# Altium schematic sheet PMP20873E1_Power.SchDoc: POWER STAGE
size 431 x 279 mm; Date: Not shown in title block; ApprovedBy: Not shown in title block; CheckedBy: Not shown in title block; Author: Not shown in title block; CompanyName: Not shown in title block; DrawnBy: Eric Faraci; Engineer: Not shown in title block; Organization: Not shown in title block; Address1: Not shown in title block; Address2: Not shown in title block; Address3: Not shown in title block; Address4: Not shown in title block; DocumentNumber: 1; Revision: E1; SheetNumber: 2; SheetTotal: 8; PageSetup: Record=PageOptions¦CenterHorizontal=True¦CenterVertical=True¦PrintScale=0.96¦XCorrection=1.00¦YCorrection=1.00¦PrintKind=0¦BorderSize=5000000¦LeftOffset=0¦BottomOffset=0¦Orientation=2¦PaperLength=1000¦PaperWidth=1000¦Scale=100¦PaperSource=15¦PrintQuality=600¦MediaType=1¦DitherType=10¦PaperKind=11x17¦PrintScaleMode=1
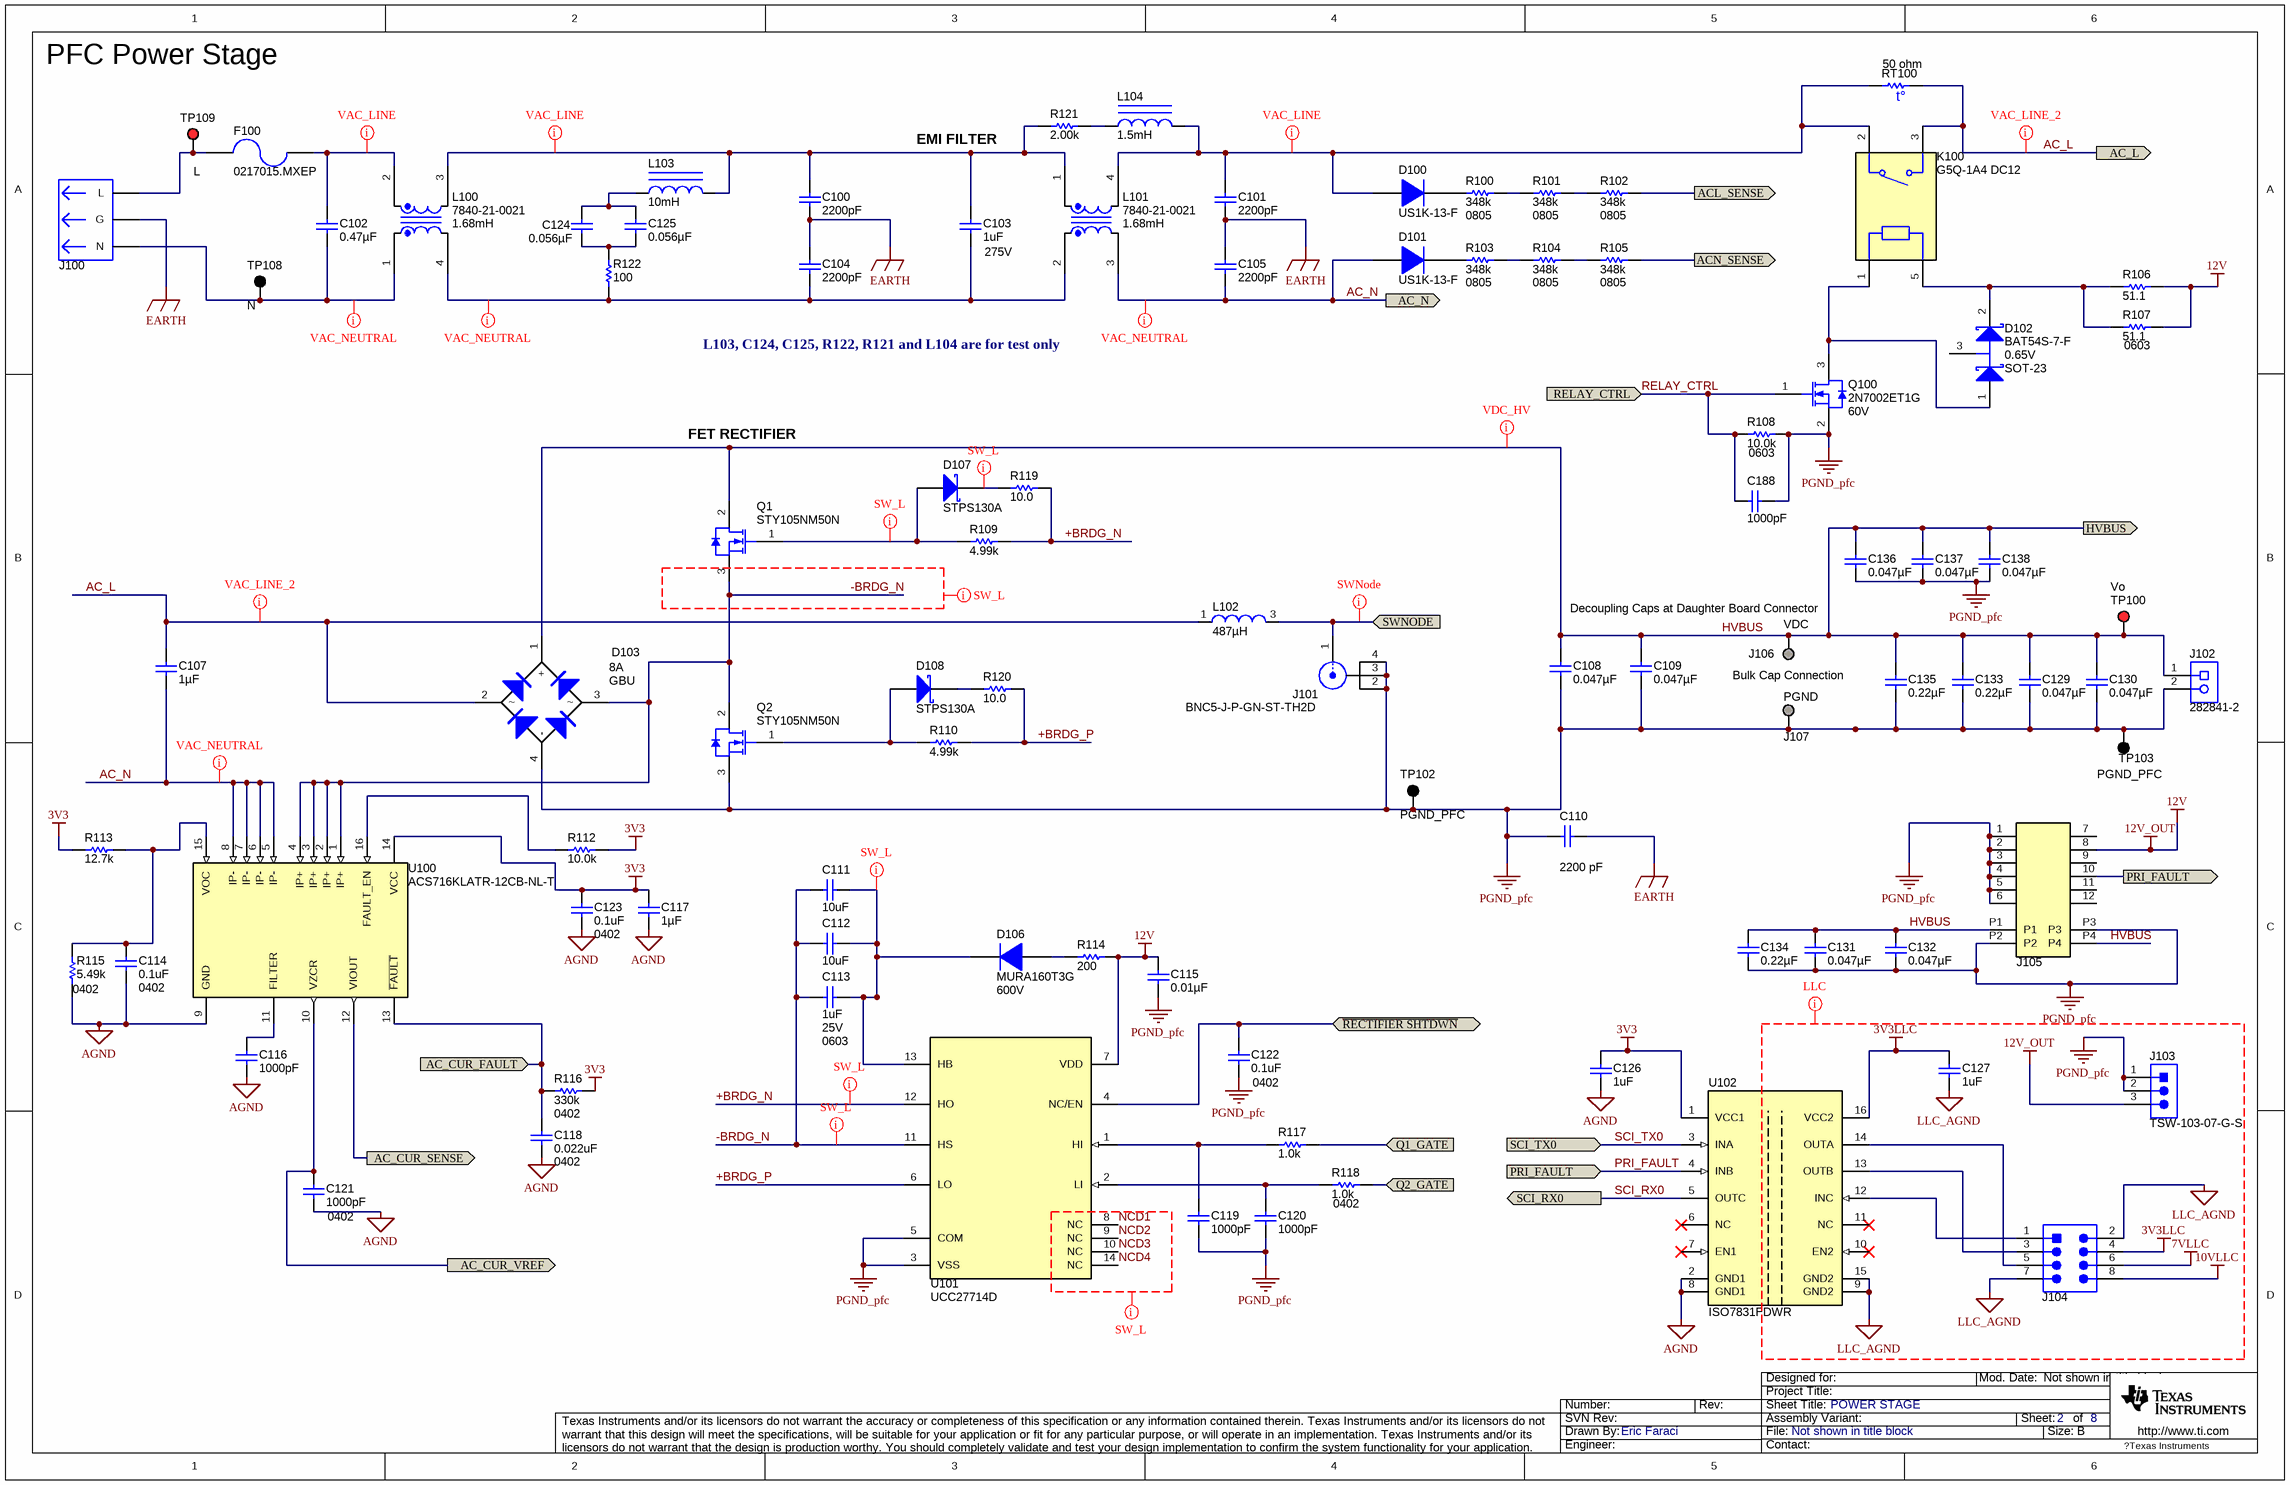
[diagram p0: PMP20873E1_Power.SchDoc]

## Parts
C100  ValueDisplayed: 2200pF  [CAPRD500W60D800H850]  (hidden comment: DE2E3KY222MA2BM01)
C101  ValueDisplayed: 2200pF  [CAPRD500W60D800H850]  (hidden comment: DE2E3KY222MA2BM01)
C102  ValueDisplayed: 0.47µF  [CAPRR2250W80L2550T850H1750]  (hidden comment: ECQ-U2A474ML)
C103  Value2: 275V  ValueDisplayed: 1uF  [CAPRR2250W80L2550T850H1750]  (hidden comment: R46KN-4100--P1 M)
C104  ValueDisplayed: 2200pF  [CAPRD500W60D800H850]  (hidden comment: DE2E3KY222MA2BM01)
C105  ValueDisplayed: 2200pF  [CAPRD500W60D800H850]  (hidden comment: DE2E3KY222MA2BM01)
C107  ValueDisplayed: 1µF  [MPK_1800x950]  (hidden comment: 450MPK105J)
C108  ValueDisplayed: 0.047µF  [1210]  (hidden comment: GRM32DR72J473KW01L)
C109  ValueDisplayed: 0.047µF  [1210]  (hidden comment: GRM32DR72J473KW01L)
C110  value 2200 pF  [CAPRD1000W60D900H1200]  (hidden comment: C921U222MYWDBA7317)
C111  ValueDisplayed: 10uF  [0805_HV]  (hidden comment: 0805YD106MAT2A)
C112  ValueDisplayed: 10uF  [0805_HV]  (hidden comment: 0805YD106MAT2A)
C113  ValueDisplayed: 1uF  Value2: 25V  [0603]  (hidden comment: C1608X7R1E105K080AB)
C114  ValueDisplayed: 0.1uF  [0402]  (hidden comment: GRM155R70J104KA01D)
C115  ValueDisplayed: 0.01µF  [0603]  (hidden comment: C0603X103K5RACTU)
C116  ValueDisplayed: 1000pF  [0603]  (hidden comment: C1608X7R1H102K)
C117  ValueDisplayed: 1µF  [0603]  (hidden comment: GRM185R60J105KE26D)
C118  ValueDisplayed: 0.022uF  [0402]  (hidden comment: GRM155R70J223KA01D)
C119  ValueDisplayed: 1000pF  [0402]  (hidden comment: C1005X7R1H102K)
C120  ValueDisplayed: 1000pF  [0402]  (hidden comment: GRM155R60J102KA01D)
C121  ValueDisplayed: 1000pF  [0402]  (hidden comment: GRM155R60J102KA01D)
C122  ValueDisplayed: 0.1uF  [0402]  (hidden comment: GRM155R70J104KA01D)
C123  ValueDisplayed: 0.1uF  [0402]  (hidden comment: GRM155R70J104KA01D)
C124  ValueDisplayed: 0.056µF  [2220_330_N]  (hidden comment: GA355XR7GB563KW06L)
C125  ValueDisplayed: 0.056µF  [2220_330_N]  (hidden comment: GA355XR7GB563KW06L)
C126  ValueDisplayed: 1uF  [0603]  (hidden comment: C1608X7R1E105K080AB)
C127  ValueDisplayed: 1uF  [0603]  (hidden comment: C1608X7R1E105K080AB)
C129  ValueDisplayed: 0.047µF  [1210]  (hidden comment: GRM32DR72J473KW01L)
C130  ValueDisplayed: 0.047µF  [1210]  (hidden comment: GRM32DR72J473KW01L)
C131  ValueDisplayed: 0.047µF  [1210]  (hidden comment: GRM32DR72J473KW01L)
C132  ValueDisplayed: 0.047µF  [1210]  (hidden comment: GRM32DR72J473KW01L)
C133  ValueDisplayed: 0.22µF  [2220]  (hidden comment: GRM55DR72J224KW01L)
C134  ValueDisplayed: 0.22µF  [2220]  (hidden comment: GRM55DR72J224KW01L)
C135  ValueDisplayed: 0.22µF  [2220]  (hidden comment: GRM55DR72J224KW01L)
C136  ValueDisplayed: 0.047µF  [1210]  (hidden comment: GRM32DR72J473KW01L)
C137  ValueDisplayed: 0.047µF  [1210]  (hidden comment: GRM32DR72J473KW01L)
C138  ValueDisplayed: 0.047µF  [1210]  (hidden comment: GRM32DR72J473KW01L)
C188  ValueDisplayed: 1000pF  [0603]  (hidden comment: GRM188R71C102KA01D)
D100  US1K-13-F  [SMA]
D101  US1K-13-F  [SMA]
D102  BAT54S-7-F  value 0.65V  [SOT-23]
D103  Value1: 8A  [GBU]  (hidden comment: GBU8J-BP)
D106  MURA160T3G  value 600V  [SMA]
D107  STPS130A  [SMA]
D108  STPS130A  [SMA]
F100  0217015.MXEP  [Fuse_217_015_Verical]
J100  703W-00/54  [CONN_QUALTEK-703W-0054]  (value not drawn)
J101  BNC5-J-P-GN-ST-TH2D  [Samtec_BNC5-J-P-GN-ST-TH2D]
J102  282841-2  [TEC_282841-2]
J103  TSW-103-07-G-S  [TSW-103-07-G-S]
J104  TSW-104-07-G-D  [TSW-104-07-G-D]  (value not drawn)
J105  PESC-02-12-02-01-L-RA-LC  [Samtec_PESC-02-12-02-01-x-RA-LC]  (value not drawn)
J106  VDC  [Mill-Max_0312-0-15-15-34-27-10-0]
J107  PGND  [Mill-Max_0312-0-15-15-34-27-10-0]
K100  G5Q-1A4 DC12  [Relay_G5Q-1A4]
L100  7840-21-0021  ValueDisplayed: 1.68mH  [7840-21-0021]
L101  7840-21-0021  ValueDisplayed: 1.68mH  [7840-21-0021]
L102  ValueDisplayed: 487µH  [IND_7840-09-0014]  (hidden comment: G164005LF)
L103  ValueDisplayed: 10mH  [ASPI-0403S]  (hidden comment: ASPI-0403S-103M-T)
L104  ValueDisplayed: 1.5mH  [LQH43M]  (hidden comment: LQH43MN152K03L)
Q1  STY105NM50N  [TO-247]
Q2  STY105NM50N  [TO-247]
Q100  2N7002ET1G  value 60V  [SOT-23]
R100  value 348k  PackageReference: 0805  [0805_HV]  (hidden comment: RT0805BRD07348KL)
R101  value 348k  PackageReference: 0805  [0805_HV]  (hidden comment: RT0805BRD07348KL)
R102  value 348k  PackageReference: 0805  [0805_HV]  (hidden comment: RT0805BRD07348KL)
R103  value 348k  PackageReference: 0805  [0805_HV]  (hidden comment: RT0805BRD07348KL)
R104  value 348k  PackageReference: 0805  [0805_HV]  (hidden comment: RT0805BRD07348KL)
R105  value 348k  PackageReference: 0805  [0805_HV]  (hidden comment: RT0805BRD07348KL)
R106  value 51.1  [0603]  (hidden comment: CRCW060351R1FKEA)
R107  value 51.1  [0603]  (hidden comment: CRCW060351R1FKEA)
R108  value 10.0k  [0603]  (hidden comment: RC0603FR-0710KL)
R109  ValueDisplayed: 4.99k  [0805_HV]  (hidden comment: ERJ-6ENF4991V)
R110  ValueDisplayed: 4.99k  [0805_HV]  (hidden comment: ERJ-6ENF4991V)
R112  value 10.0k  [0402]  (hidden comment: CRCW040210K0FKED)
R113  value 12.7k  [0402]  (hidden comment: CRCW040212K7FKED)
R114  value 200  [0603]  (hidden comment: CRCW0603200RFKEA)
R115  value 5.49k  [0402]  (hidden comment: CRCW04025K49FKED)
R116  value 330k  [0402]  (hidden comment: CRCW0402330KJNED)
R117  value 1.0k  [0402]  (hidden comment: CRCW04021K00JNED)
R118  value 1.0k  [0402]  (hidden comment: CRCW04021K00JNED)
R119  ValueDisplayed: 10.0  [0805_HV]  (hidden comment: CRCW080510R0FKEA)
R120  ValueDisplayed: 10.0  [0805_HV]  (hidden comment: CRCW080510R0FKEA)
R121  ValueDisplayed: 2.00k  [1206]  (hidden comment: CRCW12062K00FKEA)
R122  ValueDisplayed: 100  [1206]  (hidden comment: CRCW1206100RFKEA)
RT100  value 50 ohm  [TDK_B751]  (hidden comment: B59751B0120A070)
TP100  Vo  [Keystone5000]
TP102  PGND_PFC  [Keystone5001]
TP103  PGND_PFC  [Keystone5001]
TP108  N  [Keystone5001]
TP109  L  [Keystone5000]
U100  ACS716KLATR-12CB-NL-T  [SOIC-16]
U101  UCC27714D  [D0014A_N]
U102  ISO7831FDWR  [DW0016B_N]

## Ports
AC_CUR_FAULT, AC_CUR_SENSE, AC_CUR_VREF, AC_L, AC_N, ACL_SENSE, ACN_SENSE, HVBUS, PRI_FAULT (in), PRI_FAULT (out), Q1_GATE (in), Q2_GATE (in), RELAY_CTRL, SCI_RX0, SCI_TX0 (in), SWNODE, ~{RECTIFIER SHTDWN} (bidir)

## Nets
3V3: C117.1 C123.1 C126.2 R112.2 R113.2 R116.1 U100.14(VCC) U102.1(VCC1)
3V3LLC: C127.2 J104.4 U102.16(VCC2)
7VLLC: J104.6
10VLLC: J104.8
12V: C115.1 J103.3 J105.8 R106.2 R107.2 R114.2 U101.7(VDD)  [also labelled 12V_OUT]
AGND: C114.2 C116.2 C117.2 C118.1 C121.2 C123.2 C126.1 R115.1 U100.9(GND) U102.2(GND1) U102.8(GND1)
EARTH: C100.2 C101.2 C104.1 C105.1 C110.1 J100.3(G)
LLC_AGND: C127.1 J104.2 J104.7 U102.9(GND2) U102.15(GND2)
PGND_pfc: C108.2 C109.2 C110.2 C115.2 C119.2 C120.2 C122.2 C129.2 C130.2 C131.2 C132.2 C133.1 C134.2 C135.1 C136.2 C137.2 C138.2 C188.1 D103.4(-) J101.2 J101.3 J101.4 J102.2 J103.1 J103.2 J105.1 J105.2 J105.3 J105.4 J105.5 J105.6 J105.P2 J105.P3 J107.1 Q2.3(S) Q100.2(S) R108.2 TP102.1 TP103.1 U101.3(VSS) U101.5(COM)
+BRDG_N: R109.2 R119.2 U101.12(HO)
+BRDG_P: R110.2 R120.2 U101.6(LO)
-BRDG_N: C111.2 C112.2 C113.1 D103.3 Q1.3(S) Q2.2(D) U100.1(IP+) U100.2(IP+) U100.3(IP+) U100.4(IP+) U101.11(HS)
~{RECTIFIER SHTDWN}: C122.1 U101.4(NC/EN) ; port ~{RECTIFIER SHTDWN}
AC_CUR_FAULT: C118.2 R116.2 U100.13(~{FAULT}) ; port AC_CUR_FAULT
AC_CUR_SENSE: U100.12(VIOUT) ; port AC_CUR_SENSE
AC_CUR_VREF: C121.1 U100.10(VZCR) ; port AC_CUR_VREF
AC_L: C107.1 D103.2 K100.3 L102.1 RT100.2 ; port AC_L
AC_N: C105.2 C107.2 D101.2(A) L101.3 U100.5(IP-) U100.6(IP-) U100.7(IP-) U100.8(IP-) ; port AC_N
ACL_SENSE: R102.1 ; port ACL_SENSE
ACN_SENSE: R105.1 ; port ACN_SENSE
HVBUS: C108.1 C109.1 C129.1 C130.1 C131.1 C132.1 C133.2 C134.1 C135.2 C136.1 C137.1 C138.1 D103.1(+) J102.1 J105.P1 J105.P4 J106.1 Q1.2(D) TP100.1 ; port HVBUS
NCD1: U101.8(NC)
NCD2: U101.9(NC)
NCD3: U101.10(NC)
NCD4: U101.14(NC)
PRI_FAULT: J105.10 U102.4(INB) ; port PRI_FAULT
Q1_GATE: R117.2 ; port Q1_GATE
Q2_GATE: R118.2 ; port Q2_GATE
RELAY_CTRL: C188.2 Q100.1(G) R108.1 ; port RELAY_CTRL
SCI_RX0: U102.5(OUTC) ; port SCI_RX0
SCI_TX0: U102.3(INA) ; port SCI_TX0
SWNODE: J101.1 L102.3 ; port SWNODE
NetC100_1: C100.1 C103.1 L100.3 L101.1 L103.2 R121.1
NetC101_1: C101.1 D100.2(A) K100.2 L101.4 L104.2 RT100.1
NetC102_1: C102.1 F100.2 L100.2
NetC102_2: C102.2 J100.2(N) L100.1 TP108.1
NetC103_2: C103.2 C104.2 L100.4 L101.2 R122.1
NetC111_1: C111.1 C112.1 C113.2 D106.1(K) U101.13(HB)
NetC114_1: C114.1 R113.1 R115.2 U100.15(VOC)
NetC116_1: C116.1 U100.11(FILTER)
NetC119_1: C119.1 R117.1 U101.1(HI)
NetC120_1: C120.1 R118.1 U101.2(LI)
NetC124_1: C124.1 C125.1 L103.1
NetC124_2: C124.2 C125.2 R122.2
NetD100_1: D100.1(K) R100.2
NetD101_1: D101.1(K) R103.2
NetD102_1: D102.1(A) K100.1 Q100.3(D)
NetD102_2: D102.2(K) K100.5 R106.1 R107.1
NetD106_2: D106.2(A) R114.1
NetD107_1: D107.1(K) R119.1
NetD107_2: D107.2(A) Q1.1(G) R109.1
NetD108_1: D108.1(K) R120.1
NetD108_2: D108.2(A) Q2.1(G) R110.1
NetF100_1: F100.1 J100.1(L) TP109.1
NetJ104_1: J104.1 U102.12(INC)
NetJ104_3: J104.3 U102.13(OUTB)
NetJ104_5: J104.5 U102.14(OUTA)
NetL104_1: L104.1 R121.2
NetR100_1: R100.1 R101.2
NetR101_1: R101.1 R102.2
NetR103_1: R103.1 R104.2
NetR104_1: R104.1 R105.2
NetR112_1: R112.1 U100.16(FAULT_EN)

Not connected (* = marked no-connect by the designer): D102 3(C); J105 7 9 11 12; U102 6(NC)* 7(EN1)* 10(EN2)* 11(NC)*

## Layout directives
net class VAC_NEUTRAL: AC_N, NetC102_2, NetC103_2
net class VAC_LINE: NetC100_1, NetC101_1, NetC102_1
net class VAC_LINE_2: AC_L
net class SW_L: +BRDG_N, -BRDG_N, NCD1, NCD2, NCD3, NCD4, NetC111_1, NetD107_1, NetD107_2
net class LLC: 3V3LLC, 7VLLC, 10VLLC, 12V_OUT, LLC_AGND, PGND_pfc
net class VDC_HV: HVBUS
net class SWNode: SWNODE

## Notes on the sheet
- PFC Power Stage
- EMI FILTER
- L103, C124, C125, R122, R121 and L104 are for test only
- FET RECTIFIER
- Decoupling Caps at Daughter Board Connector
- Bulk Cap Connection

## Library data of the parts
C100 C101 C104 C105 = DE2E3KY222MA2BM01: CAP, CERM, 2200pF, 250V, +/-20%, KY, Radial D8x5mm; Manufacturer: MuRata; Polarized: N; CompType: Capacitor; U/M: EA; Cap_F: 0.0000000022; Tolerance_%: 20; Value1: Unknown; VDC_V: 250; TaMin_C: -25; TaMax_C: 85
C102 = ECQ-U2A474ML: CAP, Film, 0.47 µF, 275 V, +/- 20%, TH; Manufacturer: Panasonic; Polarized: N; CompType: Capacitor; Value: 0.47uF; U/M: EA; Cap_F: 0.00000047; Tolerance_%: 20; Value1: Unknown; VDC_V: 275; Value2: 275V; TaMin_C: -40; TaMax_C: 100; Cap_Case: Radial 25x8.5x18.5; AEC Category: Q200
C103 = ECQ-U2A474ML: CAP, Film, 1uF, 275V, +/-20%, TH; Manufacturer: Panasonic; Alternate PartNumber: R46KN410000P1M; Alternate Manufacturer: Kemet; Polarized: N; CompType: Capacitor; U/M: EA; Cap_F: 0.00000047; Tolerance_%: 20; Value1: Unknown; VDC_V: 275; TaMin_C: -40; TaMax_C: 100; Cap_Case: Radial 26x12x19.5
C107 = 450MPK105J: CAP, Film, 1 µF, 450 V, +/- 5%, TH; Manufacturer: Rubycon; Polarized: N; CompType: Capacitor; Value: 1uF; U/M: EA; Cap_F: 0.000001; Tolerance_%: 5; Value1: Unknown; VDC_V: 450; Value2: 450V; TaMin_C: -40; TaMax_C: 105; Cap_Case: 18x9.5mm; AEC Category: Q200
C108 C109 C129-C132 C136-C138 = GRM32DR72J473KW01L: CAP, CERM, 0.047 µF, 630 V, +/- 10%, X7R, 1210; Manufacturer: MuRata; Polarized: N; CompType: Capacitor; Value: 0.047uF; U/M: EA; Cap_F: 0.000000047; Tolerance_%: 10; Value1: Unknown; VDC_V: 630; Value2: 630V; TaMin_C: -55; TaMax_C: 125; AEC Category: Q200
C110 = DE1E3KX222MA4BL01: CAP, CERM, 2200pF, 250V, +/-20%, E, Cap, 7x12x9 mm TH; Manufacturer: Kemet; Tolerance_%: 20 %; Capacitance - nF: 2.2 nF; Capacitance - uF: 0.0022 uF; Case Diameter: 9 mm; TempCo: Y5U; Product Status: New Product
C111 C112 = 0805YD106MAT2A: CAP, CERM, 10uF, 16V, +/-20%, X5R, 0805; Manufacturer: AVX; Polarized: N; CompType: Capacitor; U/M: EA; Cap_F: 0.00001; Tolerance_%: 20; Value1: Unknown; VDC_V: 16; TaMin_C: -55; TaMax_C: 85; Cap_Case: 0805
C113 C126 C127 = C1608X7R1E105K080AB: CAP, CERM, 1uF, 25V, +/-10%, X7R, 0603; Manufacturer: TDK; Polarized: N; CompType: Capacitor; U/M: EA; Cap_F: 0.000001; Tolerance_%: 10; Value1: Unknown; VDC_V: 25; TaMin_C: -55; TaMax_C: 125
C114 C122 C123 = GRM155R70J104KA01D: CAP, CERM, 0.1uF, 6.3V, +/-10%, X7R, 0402; Manufacturer: MuRata; Polarized: N; CompType: Capacitor; U/M: EA; Cap_F: 0.0000001; Tolerance_%: 10; Value1: Unknown; VDC_V: 6.3; TaMin_C: -55; TaMax_C: 125
C115 = C0603X103K5RACTU: CAP, CERM, 0.01uF, 50V, +/-10%, X7R, 0603; Manufacturer: Kemet; Polarized: N; CompType: Capacitor; U/M: EA; Cap_F: 0.00000001; Tolerance_%: 10; Value1: Unknown; VDC_V: 50; TaMin_C: -55; TaMax_C: 125
C116 = C1608X7R1H102K: CAP, CERM, 1000pF, 50V, +/-10%, X7R, 0603; Manufacturer: TDK; Polarized: N; CompType: Capacitor; U/M: EA; Cap_F: 0.000000001; Tolerance_%: 10; ESR_Ohm: 0.24; Value1: 0.24 ohm; VDC_V: 50; TaMin_C: -55; TaMax_C: 125
C117 = GRM185R60J105KE26D: CAP, CERM, 1uF, 6.3V, +/-10%, X5R, 0603; Manufacturer: MuRata; Polarized: N; CompType: Capacitor; U/M: EA; Cap_F: 0.000001; Tolerance_%: 10; Value1: Unknown; VDC_V: 6.3; TaMin_C: -55; TaMax_C: 85
C118 = GRM155R70J223KA01D: CAP, CERM, 0.022uF, 6.3V, +/-10%, X7R, 0402; Manufacturer: MuRata; Polarized: N; CompType: Capacitor; U/M: EA; Cap_F: 0.000000022; Tolerance_%: 10; Value1: Unknown; VDC_V: 6.3; TaMin_C: -55; TaMax_C: 125
C119 = C1005X7R1H102K: CAP, CERM, 1000pF, 50V, +/-10%, X7R, 0402; Manufacturer: TDK; Polarized: N; CompType: Capacitor; U/M: EA; Cap_F: 0.000000001; Tolerance_%: 10; ESR_Ohm: 0.2381; Value1: 0.2381 ohm; VDC_V: 50; TaMin_C: -55; TaMax_C: 125
C120 C121 = GRM155R60J102KA01D: CAP, CERM, 1000pF, 6.3V, +/-10%, X5R, 0402; Manufacturer: MuRata; Polarized: N; CompType: Capacitor; U/M: EA; Cap_F: 0.000000001; Tolerance_%: 10; Value1: Unknown; VDC_V: 6.3; TaMin_C: -55; TaMax_C: 85
C124 C125 = GA355XR7GB563KW06L: CAP, CERM, 0.056 µF, 250 V, +/- 10%, X7R, 2220; Manufacturer: MuRata; Polarized: N; CompType: Capacitor; Value: 0.056uF; U/M: EA; Cap_F: 0.000000056; Tolerance_%: 10; Value1: Unknown; VDC_V: 250; Value2: 250V; TaMin_C: -55; TaMax_C: 125; Cap_Case: 2220; AEC Category: Q200
C133-C135 = GRM55DR72J224KW01L: CAP, CERM, 0.22 µF, 630 V, +/- 10%, X7R, 2220; Manufacturer: MuRata; Polarized: N; CompType: Capacitor; Value: 0.22uF; U/M: EA; Cap_F: 0.00000022; Tolerance_%: 10; Value1: Unknown; VDC_V: 630; Value2: 630V; TaMin_C: -55; TaMax_C: 125; AEC Category: Q200
C188 = GRM188R71C102KA01D: CAP, CERM, 1000pF, 16V, +/-10%, X7R, 0603; Manufacturer: MuRata; Polarized: N; CompType: Capacitor; U/M: EA; Cap_F: 0.000000001; Tolerance_%: 10; Value1: Unknown; VDC_V: 16; TaMin_C: -55; TaMax_C: 125
D100 D101 = US1K-13-F: Diode, Fast Rectifier, 800 V, 1 A, SMA; Manufacturer: Diodes Inc.; U/M: EA; Vf_V: 1.7; Value: 800V; Value1: 1A; Value2: 1.7V; Io_A: 1; Vr_V: 800; TJmax_C: 150; AEC Category: Q101
D102 = BAT54S-7-F: Diode, Schottky, 30V, 0.2A, SOT-23; Manufacturer: Diodes Inc.; U/M: EA; Vf_V: 0.65; Io_A: 0.2; Vr_V: 30; TJmax_C: 125
D103 = GBU8J-BP: Diode, Switching-Bridge, 420V, 8A, TH; Manufacturer: Micro Commercial Components; Value: 1V; U/M: EA; Vf_V: 1; Io_A: 8; Vr_V: 420; TJmax_C: 175
D106 = MURA160T3G: Diode, Ultrafast, 600V, 1A, SMA; Manufacturer: ON Semiconductor; U/M: EA; Vf_V: 1.05; Value2: 1.05V; Io_A: 1; Vr_V: 600; TJmax_C: 175
D107 D108 = STPS130A: Diode, Schottky, 30 V, 1 A, SMA; Manufacturer: STMicroelectronics; U/M: EA; Vf_V: 0.46; Value: 30V; Value1: 1A; Value2: 0.46V; Io_A: 1; Vr_V: 30; TJmax_C: 150; AEC Category: Q101
F100 = 0217015.MXEP: Fuse, 15 A, 250 V, TH; Manufacturer: Littelfuse; U/M: EA; VDC_V: 250; Irating_A: 15; Rtyp_Ohm: 0.04; MeltingTyp: 617.135; Vdrop: 0.13
J100 = 703W-00/54: AC Receptacle, 10A 250VAC; Manufacturer: Qualtek Electronics Corporation; SymbolCreator: a0799628; CompType: Connector; U/M: EA
J101 = BNC5-J-P-GN-ST-TH2D: 50 OHM BNC ELEVATED STRAIGHT JACK, TH; Manufacturer: Samtec; SymbolCreator: Altium; Gender: Male; ContactFinish: Gold
J102 = 282841-2: Terminal Block, 2x1, 5.08mm, TH; Manufacturer: TE Connectivity; SymbolCreator: a0412235; U/M: EA
J103 = TSW-103-07-G-S: Header, 100mil, 3x1, Gold, TH; Manufacturer: Samtec; SymbolCreator: a0799628; Pitch_mm: 2.54; Gender: Male; Shrouded: N; Row_Count: 1; Current_A: 6.3; Voltage_V: 550; Cert_CSA: Y
J104 = TSW-104-07-G-D: Header, 100mil, 4x2, Gold, TH; Manufacturer: Samtec; SymbolCreator: a0411947; Pitch_mm: 2.54; Gender: Male; Shrouded: N; Row_Count: 2; Current_A: 6.3; Voltage_V: 550; Cert_CSA: Y
J105 = PESC-02-12-02-01-L-RA-LC: Signal Power Combo Socket Strip, 4x3, 4 Power Group, R/A, Gold, TH; Manufacturer: Samtec; SymbolCreator: Altium; CompType: Power Connector; Pitch_mm: 2.54; Gender: Female; Row_Count: 3; Current_A: 40; Voltage_V: 650; Cert_UL: Y
J106 J107 = 0312-0-15-15-34-27-10-0: Pin Receptacle, .032-.046" .075" Dia, Gold, TH; Manufacturer: Mill-Max; U/M: EA
K100 = G5Q-1A4 DC12: Relay, SPST-NO (1 Form A), 10 A, 12 VDC, TH; Manufacturer: Omron Electronic Components; SymbolCreator: Altium; Coil Current: 16.7 mA; Coil Power: 200 mW; Coil Resistance: 720 ohms; Coil Type: Non Latching; Coil Voltage: 12 VDC; Contact Rating: 10 A; Turn Off Voltage (Min): 0.6 VDC; Turn On Voltage (Max): 9 VDC; Time Operate (s): 0.01; Time Release (s): 0.005
L100 L101 = 7840-21-0021: Coupled inductor, 1.68 mH,  A,  ohm, TH; Manufacturer: Nova Magnetics; SymbolCreator: a0799628; Value: 1.68mH; Ind_H: 1.7E-3
L102 = 7840-09-0014: Inductor, Toroid, Ferrite, 481 µH, 0.057 ohm, TH; Manufacturer: GCI technologies; SymbolCreator: a0411947; Value: 487uH; DCR_ohm: 0.057; Value2: A; AEC Category: Q200
L103 = ASPI-0403S-103M-T: Inductor, Wirewound, 10 mH, 0.02 A, 32.8 ohm, SMD; Manufacturer: Abracon Corporation; Value: 10mH; Ind_H: 10.0E-3; Imax_A: 0.02; DCR_ohm: 32.8; Value2: 0.02A; AEC Category: Q200; AEC Qualified: N
L104 = LQH43MN152K03L: Inductor, Wirewound, Ferrite, 1.5 mH, 0.04 A, 37 ohm, SMD; Manufacturer: MuRata; Value: 1.5mH; Ind_H: 1.5E-3; Imax_A: 0.04; DCR_ohm: 37; Value1: 37 ohm; Value2: 0.04A; AEC Category: Q200; AEC Qualified: N
Q1 Q2 = STY105NM50N: MOSFET, N-CH, 500 V, 110 A, TO-247; Manufacturer: STMicroelectronics; Alternate Manufacturer: None; U/M: EA; ChType: N; Value: 500V; VdsMax_V: 500; Value1: ? ohm; Value2: 326 nC; QgTyp_nC: 326; Vgs_V: 25; IdsMax_A: 110; AEC Category: Q101
Q100 = 2N7002ET1G: MOSFET, N-CH, 60V, 0.26A, SOT-23; Manufacturer: ON Semiconductor; Alternate Manufacturer: None; U/M: EA; ChType: N; VdsMax_V: 60; Value1: 3 ohm; Rdson45_Ohm: 3; Value2: 0.81 nC; QgTyp_nC: 0.81; Vgs_V: 20; IdsMax_A: 0.26
R100-R105 = RT0805BRD07348KL: RES, 348k ohm, 0.1%, 0.125W, 0805; Manufacturer: Yageo America; CompType: Resistor; Res_ohm: 348000; Tolerance_%: 0.1; Power_W: 0.125; VDC_V: 150; TempCo: 25 ppm/C; EIA_Code: E192; U/M: EA
R106 R107 = CRCW060351R1FKEA: RES, 51.1 ohm, 1%, 0.1W, 0603; Manufacturer: Vishay-Dale; CompType: Resistor; Value_Code: 51R1; Tolerance_%: 1; Power_W: 0.1; VDC_V: 75; TempCo: 100 ppm/C; EIA_Code: E96; U/M: EA
R108 = RC0603FR-0710KL: RES, 10.0k ohm, 1%, 0.1W, 0603; Manufacturer: Yageo America; CompType: Resistor; Res_ohm: 10000; Value_Code: 10k0; Tolerance_%: 1; Power_W: 0.1; VDC_V: 150; TempCo: 200 ppm/C; EIA_Code: E96; U/M: EA
R109 R110 = ERJ-6ENF4991V: RES, 4.99 k, 1%, 0.125 W, 0805; Manufacturer: Panasonic; CompType: Resistor; Value: 4.99k; Res_ohm: 4990; Value_Code: 4k99; Tolerance_%: 1; Power_W: 0.125; Value2: 0.125W; TempCo: 100 ppm/C; EIA_Code: E96; U/M: EA; AEC Category: Q200
R112 = CRCW040210K0FKED: RES, 10.0k ohm, 1%, 0.063W, 0402; Manufacturer: Vishay-Dale; CompType: Resistor; Res_ohm: 10000; Value_Code: 10k0; Tolerance_%: 1; Power_W: 0.063; VDC_V: 50; TempCo: 100 ppm/C; EIA_Code: E96; U/M: EA
R113 = CRCW040212K7FKED: RES, 12.7k ohm, 1%, 0.063W, 0402; Manufacturer: Vishay-Dale; CompType: Resistor; Res_ohm: 12700; Value_Code: 12k7; Tolerance_%: 1; Power_W: 0.063; VDC_V: 50; TempCo: 100 ppm/C; EIA_Code: E96; U/M: EA
R114 = CRCW0603200RFKEA: RES, 200 ohm, 1%, 0.1W, 0603; Manufacturer: Vishay-Dale; CompType: Resistor; Value_Code: 200R; Tolerance_%: 1; Power_W: 0.1; VDC_V: 75; TempCo: 100 ppm/C; EIA_Code: E96; U/M: EA
R115 = CRCW04025K49FKED: RES, 5.49k ohm, 1%, 0.063W, 0402; Manufacturer: Vishay-Dale; CompType: Resistor; Res_ohm: 5490; Value_Code: 5k49; Tolerance_%: 1; Power_W: 0.063; VDC_V: 50; TempCo: 100 ppm/C; EIA_Code: E96; U/M: EA
R116 = CRCW0402330KJNED: RES, 330k ohm, 5%, 0.063W, 0402; Manufacturer: Vishay-Dale; CompType: Resistor; Res_ohm: 330000; Tolerance_%: 5; Power_W: 0.063; VDC_V: 50; TempCo: 200 ppm/C; EIA_Code: E24; U/M: EA
R117 R118 = CRCW04021K00JNED: RES, 1.0k ohm, 5%, 0.063W, 0402; Manufacturer: Vishay-Dale; CompType: Resistor; Res_ohm: 1000; Value_Code: 1k00; Tolerance_%: 5; Power_W: 0.063; VDC_V: 50; TempCo: 200 ppm/C; EIA_Code: E24; U/M: EA
R119 R120 = CRCW080510R0FKEA: RES, 10.0, 1%, 0.125 W, 0805; Manufacturer: Vishay-Dale; CompType: Resistor; Value: 10.0; Res_ohm: 10; Value_Code: 10R0; Tolerance_%: 1; Power_W: 0.125; Value2: 0.125W; VDC_V: 150; TempCo: 100 ppm/C; EIA_Code: E96; U/M: EA
R121 = CRCW12062K00FKEA: RES, 2.00 k, 1%, 0.25 W, 1206; Manufacturer: Vishay-Dale; CompType: Resistor; Value: 2.00k; Res_ohm: 2000; Value_Code: 2k00; Tolerance_%: 1; Power_W: 0.25; Value2: 0.25W; VDC_V: 200; TempCo: 100 ppm/C; EIA_Code: E96; U/M: EA; AEC Category: Q200
R122 = CRCW1206100RFKEA: RES, 100, 1%, 0.25 W, 1206; Manufacturer: Vishay-Dale; CompType: Resistor; Value: 100; Value_Code: 100R; Tolerance_%: 1; Power_W: 0.25; Value2: 0.25W; VDC_V: 200; TempCo: 100 ppm/C; EIA_Code: E96; U/M: EA; AEC Category: Q200
RT100 = B59751B0120A070: Thermistor NTC, 50 ohm, 25%, D12.5xH16.5mm; Manufacturer: TDK; Tolerance_%: 25; TaMin_C: -40; TaMax_C: 125; U/M: EA
TP100 TP109 = 5000: Test Point, Miniature, Red, TH; Manufacturer: Keystone; CompType: Test Point Loop; U/M: EA
TP102 TP103 TP108 = 5001: Test Point, Miniature, Black, TH; Manufacturer: Keystone; CompType: Test Point Loop; U/M: EA
U100 = ACS716KLATR-12CB-NL-T: 120 kHz Bandwidth, High-Voltage Isolation Current Sensor with Integrated Overcurrent Detection; Manufacturer: Allegro Microsystems Inc; SymbolCreator: Altium
U101 = UCC27714D: High-Speed,4A, 600V High-side Low-side Gate Driver Device, D0014A; Manufacturer: Texas Instruments; SymbolCreator: a0411947; CompType: IC; U/M: EA
U102 = ISO7831FDWR: High-Performance, 8000 VPK Reinforced Triple Digital Isolator, DW0016B; Manufacturer: Texas Instruments; SymbolCreator: Altium; SizeArea_mm2: 107.12; SizeAreaWB_mm2: 152.52; SizeX_mm: 10.4; SizeY_mm: 10.3; SizeZ_mm: 2.65; CompType: IC; U/M: EA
